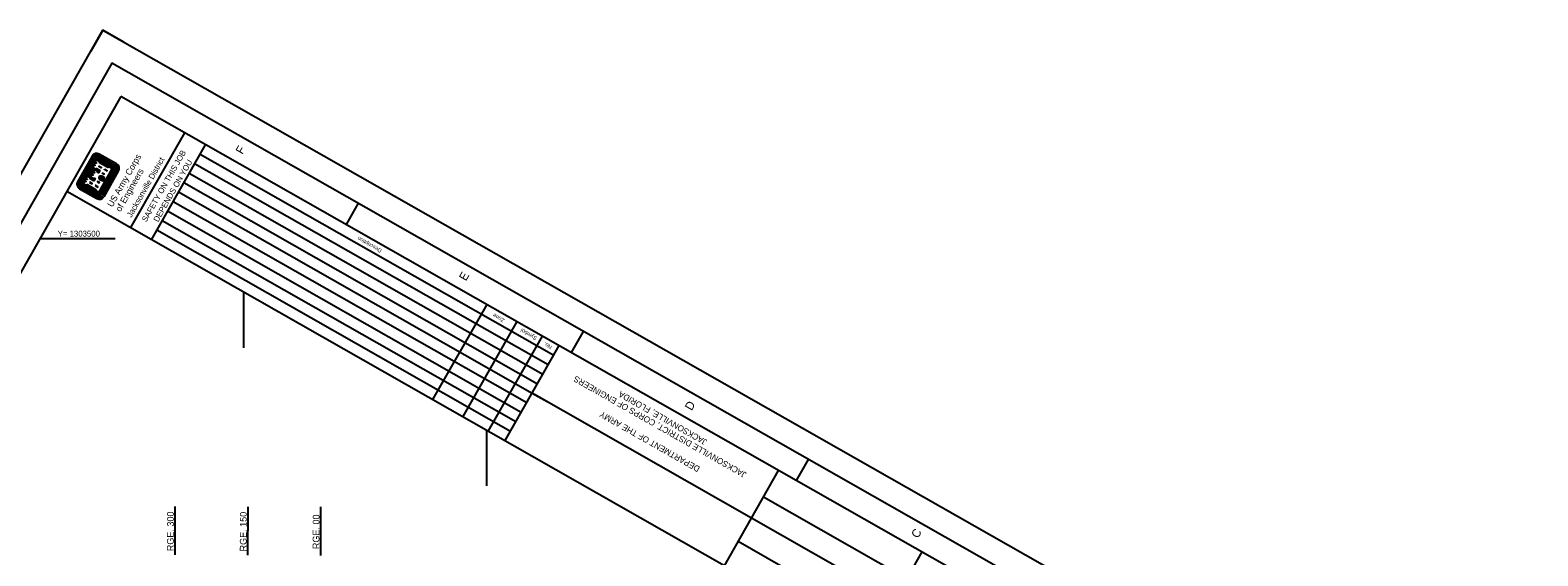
# Model space of a CAD drawing. Extents: x 515534 to 520665, y 1298425 to 1303930.
# Drawn here: x 517560 to 520665, y 1302847 to 1303930 of the extents above; entities that cross this region are included whole.
import ezdxf

# ---------------------------------------------------------------- set-up
doc = ezdxf.new("R2010")
doc.units = 0
for name, color, linetype in [('G-ANNO-NPLT', 7, 'Continuous'), ('G-ANNO-TEXT-LOGO', 7, 'Continuous'), ('G-ANNO-TEXT-TTLB', 7, 'Continuous'), ('G-ANNO-TTLB', 7, 'Continuous'), ('V-ALGN-TEXT', 7, 'Continuous'), ('V-TOPO-COOR-STAT', 7, 'Continuous')]:
    doc.layers.add(name, color=color, linetype=linetype)

msp = doc.modelspace()

# ---------------------------------------------------------------- linework, layer by layer
at = {"layer": 'G-ANNO-NPLT'}
msp.add_lwpolyline([(515533.7, 1300105.7), (517709.3, 1303930.2), (520664.6, 1302249.1), (518489, 1298424.6)], close=True, dxfattribs=at)
msp.add_lwpolyline([(517752.8, 1303905.4), (517709.3, 1303930.2), (517684.6, 1303886.7)], dxfattribs=at)
at = {"layer": 'G-ANNO-TEXT-LOGO'}
for p, q in [((517687.6, 1303670.8), (517657.6, 1303618)), ((517660.3, 1303616.4), (517690.4, 1303669.2)), ((517693.4, 1303667.6), (517663.3, 1303614.7)), ((517694.1, 1303667.1), (517664.1, 1303614.3)), ((517694.9, 1303666.7), (517664.9, 1303613.8)), ((517695.6, 1303666.3), (517665.6, 1303613.4)), ((517696.4, 1303665.8), (517666.3, 1303613)), ((517696.3, 1303664.5), (517730.9, 1303644.8)), ((517696.7, 1303665.2), (517732.1, 1303645.1)), ((517697.2, 1303666), (517732.8, 1303645.7)), ((517697.6, 1303666.8), (517733.3, 1303646.5)), ((517698, 1303667.5), (517733.6, 1303647.2)), ((517698.5, 1303668.2), (517734.1, 1303648)), ((517698.9, 1303669), (517734.5, 1303648.7)), ((517700.6, 1303672), (517736.2, 1303651.7)), ((517737.9, 1303654.6), (517702.2, 1303674.8)), ((517677.5, 1303630.9), (517686.7, 1303647.1)), ((517678.2, 1303630.5), (517687.4, 1303646.7)), ((517678.9, 1303630.1), (517688.1, 1303646.3)), ((517679.7, 1303629.6), (517688.9, 1303645.8)), ((517680.5, 1303629.2), (517689.7, 1303645.4)), ((517681.2, 1303628.8), (517690.4, 1303645)), ((517682, 1303628.4), (517691.2, 1303644.5)), ((517730.9, 1303644.8), (517702, 1303594.1)), ((517732.1, 1303645.1), (517702.4, 1303592.9)), ((517733.1, 1303645), (517703, 1303592.1)), ((517703.6, 1303659.5), (517721.7, 1303649.3)), ((517733.8, 1303644.6), (517703.7, 1303591.7)), ((517703.9, 1303658.4), (517720.5, 1303648.9)), ((517734.6, 1303644.1), (517704.5, 1303591.3)), ((517735.3, 1303643.7), (517705.3, 1303590.8)), ((517736, 1303643.3), (517706, 1303590.4)), ((517739.1, 1303641.6), (517709, 1303588.7)), ((517711.9, 1303587.1), (517741.9, 1303639.9)), ((517661.6, 1303603.4), (517697.2, 1303583.1)), ((517698.8, 1303585.9), (517663.2, 1303606.2)), ((517664.9, 1303609.2), (517700.5, 1303588.9)), ((517665.3, 1303610), (517701, 1303589.7)), ((517665.7, 1303610.7), (517701.4, 1303590.4)), ((517666.2, 1303611.5), (517701.8, 1303591.2)), ((517666.6, 1303612.3), (517702.3, 1303592)), ((517667.1, 1303613), (517702.4, 1303592.9)), ((517667.5, 1303613.7), (517702, 1303594.1)), ((517675.4, 1303610), (517693.6, 1303599.7)), ((517676.6, 1303610.4), (517693.2, 1303600.9)), ((517709.4, 1303618.9), (517703.6, 1303622.2)), ((517709.8, 1303619.6), (517704, 1303622.9)), ((517710.2, 1303620.4), (517704.4, 1303623.7)), ((517710.7, 1303621.1), (517704.8, 1303624.4)), ((517711.1, 1303621.8), (517705.2, 1303625.1)), ((517711.7, 1303622.9), (517705.8, 1303626.2)), ((517712, 1303623.6), (517706.2, 1303626.9)), ((517712.5, 1303624.4), (517706.7, 1303627.7)), ((517712.9, 1303625.1), (517707.1, 1303628.4)), ((517713.3, 1303625.8), (517707.5, 1303629.1)), ((517709.4, 1303618.9), (517713.3, 1303625.8))]:
    msp.add_line(p, q, dxfattribs=at)
for points in [[(517667.8, 1303614.3), (517674.7, 1303610.4), (517677, 1303611.1), (517693.6, 1303601.6), (517694.3, 1303599.3), (517701.9, 1303595), (517730.1, 1303644.5), (517722.5, 1303648.8), (517720, 1303648.1), (517703.4, 1303657.6), (517702.8, 1303660), (517696, 1303663.9), (517692.3, 1303657.4), (517689.4, 1303652.3), (517686.7, 1303647.6), (517693.6, 1303643.7), (517696, 1303644.5), (517702.1, 1303641.1), (517700, 1303637.4), (517699.4, 1303637.8), (517698.7, 1303640.2), (517692, 1303644.1), (517688.3, 1303637.6), (517685.4, 1303632.5), (517682.8, 1303627.9), (517689.5, 1303624.1), (517692, 1303624.7), (517692.6, 1303624.4), (517690.5, 1303620.7), (517684.5, 1303624.2), (517683.9, 1303626.6), (517677, 1303630.5), (517673.3, 1303624), (517670.4, 1303618.9), (517667.8, 1303614.3)], [(517669, 1303614.6), (517674.7, 1303611.3), (517677.2, 1303612), (517694.4, 1303602.2), (517695.1, 1303599.8), (517701.5, 1303596.1), (517728.9, 1303644.3), (517722.4, 1303647.9), (517719.9, 1303647.2), (517702.7, 1303656.9), (517702.1, 1303659.5), (517696.4, 1303662.7), (517693.7, 1303658.1), (517696.4, 1303656.5), (517696.1, 1303656.1), (517693.5, 1303657.6), (517690.8, 1303653), (517693.5, 1303651.5), (517693.3, 1303651.1), (517690.6, 1303652.7), (517688, 1303648), (517693.7, 1303644.7), (517696.2, 1303645.4), (517703.2, 1303641.4), (517700.3, 1303636.3), (517698.7, 1303637.3), (517698, 1303639.7), (517692.3, 1303643), (517689.6, 1303638.3), (517692.3, 1303636.8), (517692.1, 1303636.4), (517689.4, 1303638), (517686.7, 1303633.3), (517689.4, 1303631.7), (517689.2, 1303631.3), (517686.5, 1303632.8), (517683.9, 1303628.2), (517689.6, 1303625), (517692.1, 1303625.6), (517693.7, 1303624.7), (517690.8, 1303619.6), (517683.8, 1303623.7), (517683.1, 1303626.1), (517677.4, 1303629.4), (517674.8, 1303624.8), (517677.5, 1303623.2), (517677.2, 1303622.8), (517674.5, 1303624.3), (517671.8, 1303619.6), (517674.5, 1303618.1), (517674.3, 1303617.8), (517671.6, 1303619.3), (517669, 1303614.6)], [(517695.2, 1303643.4), (517695.9, 1303643.6), (517700.9, 1303640.7), (517700, 1303639.2), (517699.5, 1303640.9), (517695.1, 1303643.3)], [(517701.6, 1303650.2), (517706.6, 1303647.4), (517706.4, 1303646.9), (517701.3, 1303649.8), (517701.6, 1303650.2)], [(517708.6, 1303635.8), (517712.2, 1303633.7), (517711.9, 1303633.3), (517708.4, 1303635.3), (517708.6, 1303635.8)], [(517713.1, 1303643.7), (517718.3, 1303640.7), (517718, 1303640.3), (517712.9, 1303643.2), (517713.1, 1303643.7)], [(517682.3, 1303616.4), (517687.4, 1303613.6), (517687.7, 1303614.1), (517682.6, 1303617), (517682.3, 1303616.4)], [(517685.1, 1303625.5), (517685.2, 1303624.8), (517690.2, 1303622), (517691.1, 1303623.6), (517689.4, 1303623.1), (517685, 1303625.6)], [(517693.9, 1303609.9), (517699, 1303606.9), (517699.3, 1303607.5), (517694.2, 1303610.4), (517693.9, 1303609.9)], [(517698.4, 1303617.9), (517702, 1303615.8), (517702.3, 1303616.3), (517698.7, 1303618.3), (517698.4, 1303617.9)]]:
    msp.add_lwpolyline(points, dxfattribs=at)
for centre, major_axis, start_param, end_param in [((517696.9, 1303665.5), (5.3, 9.31), 6.283169, 7.853965), ((517696.9, 1303665.5), (3.7, 6.51), 6.28317, 7.853966), ((517696.9, 1303665.5), (1.99, 3.49), 6.283169, 7.853965), ((517696.9, 1303665.5), (1.56, 2.74), 6.283169, 7.853965), ((517696.9, 1303665.5), (1.13, 1.98), 6.283169, 7.853965), ((517696.9, 1303665.5), (0.7, 1.23), 6.283169, 7.853965), ((517696.9, 1303665.5), (0.27, 0.474), 6.283169, 7.853965), ((517705.2, 1303624.1), (2.75, 4.83), 0.068795, 1.29842), ((517732.6, 1303645.2), (0.27, 0.474), 4.712373, 6.28317), ((517732.6, 1303645.2), (0.7, 1.23), 4.712373, 6.28317), ((517732.6, 1303645.2), (1.13, 1.98), 4.712373, 6.28317), ((517732.6, 1303645.2), (1.56, 2.74), 4.712373, 6.28317), ((517732.6, 1303645.2), (1.99, 3.49), 4.712373, 6.28317), ((517732.6, 1303645.2), (-3.7, -6.51), 1.570781, 3.141577), ((517732.6, 1303645.2), (5.3, 9.31), 4.712373, 6.28317), ((517666.9, 1303612.7), (5.3, 9.31), 1.57078, 3.141576), ((517666.9, 1303612.7), (3.7, 6.51), 1.57078, 3.141576), ((517666.9, 1303612.7), (1.99, 3.49), 1.57078, 3.141576), ((517666.9, 1303612.7), (1.56, 2.74), 1.57078, 3.141576), ((517666.9, 1303612.7), (1.13, 1.98), 1.57078, 3.141576), ((517666.9, 1303612.7), (0.7, 1.23), 1.57078, 3.141576), ((517666.9, 1303612.7), (0.27, 0.474), 1.57078, 3.141576), ((517706.7, 1303626.7), (-2.75, -4.83), 4.985832, 6.214359), ((517706.7, 1303626.7), (-2.32, -4.07), 4.947465, 6.21436), ((517705.2, 1303624.1), (2.32, 4.07), 0.068795, 1.335689), ((517705.2, 1303624.1), (1.89, 3.32), 0.068795, 1.335689), ((517706.7, 1303626.7), (-1.89, -3.32), 4.947465, 6.21436), ((517705.2, 1303624.1), (1.46, 2.56), 0.068794, 1.335689), ((517706.7, 1303626.7), (-1.46, -2.56), 4.947465, 6.21436), ((517705.2, 1303624.1), (1.03, 1.81), 0.068794, 1.335689), ((517706.7, 1303626.7), (-1.03, -1.81), 4.947465, 6.214359), ((517702.5, 1303592.4), (-5.3, -9.31), 6.28317, 7.853966), ((517702.5, 1303592.4), (-3.7, -6.51), 6.28317, 7.853966), ((517702.5, 1303592.4), (-1.99, -3.49), 6.28317, 7.853966), ((517702.5, 1303592.4), (-1.56, -2.74), 6.28317, 7.853966), ((517702.5, 1303592.4), (-1.13, -1.98), 6.28317, 7.853966), ((517702.5, 1303592.4), (-0.7, -1.23), 6.28317, 7.853966), ((517702.5, 1303592.4), (-0.27, -0.474), 6.28317, 7.853966)]:
    msp.add_ellipse(centre, major_axis=major_axis, ratio=0.99964, start_param=start_param, end_param=end_param, dxfattribs=at)
at = {"layer": 'G-ANNO-TTLB'}
for p, q in [((517767, 1303523.5), (517878.2, 1303719)), ((517809.4, 1303498.6), (517920.6, 1303694.2)), ((517909.7, 1303675), (518638, 1303260.7)), ((517887.5, 1303635.9), (518615.8, 1303221.6)), ((517898.6, 1303655.5), (518626.9, 1303241.2)), ((517876.3, 1303616.3), (518604.7, 1303202)), ((517635.5, 1303598.2), (520417, 1302016)), ((517854.1, 1303577.2), (518582.4, 1303162.9)), ((517865.2, 1303596.8), (518593.5, 1303182.5)), ((518235.2, 1303573.5), (518210.5, 1303530)), ((517831.8, 1303538.1), (518560.2, 1303123.8)), ((517843, 1303557.7), (518571.3, 1303143.4)), ((517820.7, 1303518.6), (518549, 1303104.3)), ((518389.3, 1303169.4), (518500.6, 1303365)), ((518451.2, 1303134.2), (518562.5, 1303329.8)), ((518503.4, 1303104.6), (518614.6, 1303300.1)), ((518698.8, 1303309.8), (518674, 1303266.3)), ((518538, 1303084.9), (518649.2, 1303280.4)), ((519340.4, 1302757.1), (518593.6, 1303182.7)), ((518593.6, 1303182.7), (518624.4, 1303165.1)), ((519162.3, 1303046.1), (519137.6, 1303002.6)), ((518989.5, 1302827.1), (519101.1, 1303023.4)), ((519070, 1302968.6), (519365.3, 1302800.7)), ((519312.7, 1302708.5), (519017.7, 1302876.6)), ((519284.5, 1302658.8), (519396.4, 1302855.4))]:
    msp.add_line(p, q, dxfattribs=at)
for points in [[(518470.3, 1298492.8), (520596.4, 1302230.3), (517728, 1303862), (515601.9, 1300124.4)], [(517746.8, 1303793.8), (515707.2, 1300208.3), (518488.6, 1298626.1), (520528.2, 1302211.6)]]:
    msp.add_lwpolyline(points, close=True, dxfattribs=at)
at = {"layer": 'V-ALGN-TEXT'}
for p, q in [((517858.2, 1302849.2), (517858.6, 1302949.2)), ((518008.2, 1302848.6), (518008.6, 1302948.6)), ((518158.2, 1302848), (518158.6, 1302948))]:
    msp.add_line(p, q, dxfattribs=at)
at = {"layer": 'V-TOPO-COOR-STAT'}
for p, q in [((517735, 1303500), (517579.6, 1303500)), ((518000, 1303275.8), (518000, 1303390.9)), ((518500, 1302991.4), (518500, 1303106.4))]:
    msp.add_line(p, q, dxfattribs=at)

# ---------------------------------------------------------------- texts
at = {"layer": 'G-ANNO-TEXT-TTLB'}
for s, height, rotation, p in [('US Army Corps', 13.086, 60.3667, (517729.1, 1303564.5)), ('Jacksonville District', 11.9, 60.3667, (517768.4, 1303543.3)), ('SAFETY ON THIS JOB', 11.9, 60.3667, (517799.2, 1303534)), ('DEPENDS ON YOU', 11.9, 60.3667, (517823.2, 1303533.9)), ('of Engineers', 13.086, 60.3667, (517745.9, 1303554.9)), ('Description', 8, 150.3667, (518284.6, 1303478.2)), ('Zone', 8, 150.3667, (518537.4, 1303334.7)), ('Symbol', 8, 150.3667, (518604.4, 1303298)), ('No.', 8, 150.3667, (518635.3, 1303279.3)), ('JACKSONVILLE DISTRICT, CORPS OF ENGINEERS', 12.5, 150.3667, (519036.4, 1303018.1)), ('JACKSONVILLE, FLORIDA', 12.5, 150.3667, (518955.2, 1303085.5)), ('DEPARTMENT OF THE ARMY', 12.5, 150.3667, (518940.4, 1303030.1))]:
    msp.add_text(s, height=height, rotation=rotation, dxfattribs=at).set_placement(p)
at = {"layer": 'G-ANNO-TTLB'}
for s, p in [('F', (517997.1, 1303673)), ('E', (518457.2, 1303412.2)), ('D', (518922.1, 1303145.2)), ('C', (519388.2, 1302882.2))]:
    msp.add_text(s, height=17.5, rotation=60.3667, dxfattribs=at).set_placement(p)
at = {"layer": 'V-ALGN-TEXT'}
for s, p in [('RGE. 300', (517855.5, 1302856.9)), ('RGE. 150', (518005.5, 1302856.4)), ('RGE. 00', (518155.5, 1302861.2))]:
    msp.add_text(s, height=13.92, rotation=89.7829, dxfattribs=at).set_placement(p)
at = {"layer": 'V-TOPO-COOR-STAT'}
msp.add_text('Y= 1303500', height=12, dxfattribs=at).set_placement((517616.5, 1303505))

doc.saveas('drawing.dxf')
